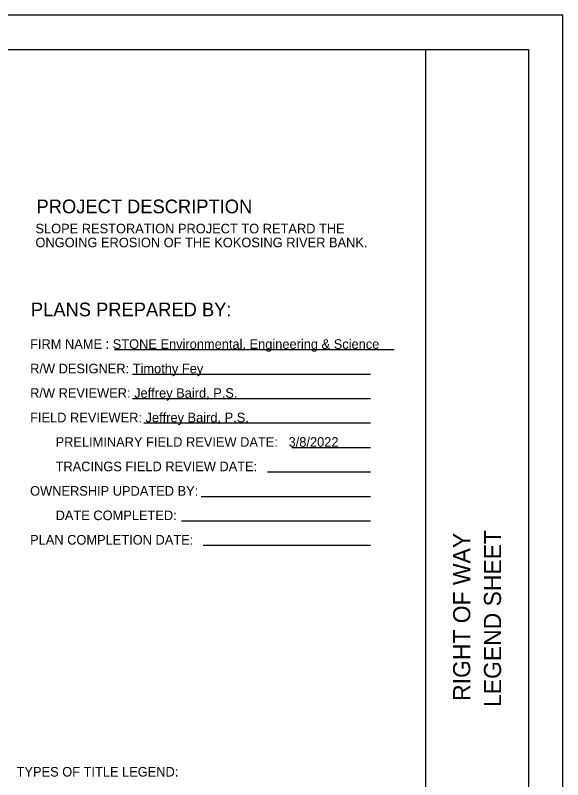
# Model space of a CAD drawing. Extents: x 0 to 104, y 0 to 37.
# Drawn here: x 26.01 to 34, y 10.84 to 22 of the extents above; entities that cross this region are included whole.
import ezdxf

# ---------------------------------------------------------------- set-up
doc = ezdxf.new("R2010")
doc.units = 0
for name, color, linetype in [('SC_Scratch3', 7, 'Continuous'), ('SH_Cut_Line', 7, 'Continuous'), ('SH_Data', 7, 'Continuous'), ('SH_Named_Boundary', 7, 'Continuous')]:
    doc.layers.add(name, color=color, linetype=linetype)

msp = doc.modelspace()

# ---------------------------------------------------------------- linework, layer by layer
at = {"layer": 'SC_Scratch3'}
msp.add_lwpolyline([(0, 0), (34, 0), (34, 22), (0, 22)], close=True, dxfattribs=at)
at = {"layer": 'SH_Data'}
for p, q in [((27.456, 17.121), (31.54, 17.121)), ((27.72, 16.764), (31.193, 16.764)), ((27.72, 16.407), (31.193, 16.407)), ((27.884, 16.05), (31.193, 16.05)), ((30.047, 15.692), (31.193, 15.692)), ((29.69, 15.335), (31.193, 15.335)), ((28.72, 14.978), (31.193, 14.978)), ((28.435, 14.621), (31.193, 14.621)), ((28.75, 14.264), (31.193, 14.264))]:
    msp.add_line(p, q, dxfattribs=at)
at = {"layer": 'SH_Named_Boundary'}
msp.add_line((32, 0.5), (32, 21.5), dxfattribs=at)
msp.add_lwpolyline([(1.5, 21.5), (33.5, 21.5), (33.5, 0.5), (1.5, 0.5)], close=True, dxfattribs=at)

# ---------------------------------------------------------------- texts
at = {"layer": 'SH_Cut_Line'}
for s, p in [('RIGHT OF WAY', (32.65, 11.993)), ('LEGEND SHEET', (33.1, 11.904))]:
    msp.add_text(s, height=0.25, rotation=90, dxfattribs=at).set_placement(p)
at = {"layer": 'SH_Data'}
for s, height, p in [('PROJECT DESCRIPTION', 0.2, (26.317, 19.11)), ('SLOPE RESTORATION PROJECT TO RETARD THE', 0.14, (26.302, 18.817)), ('ONGOING EROSION OF THE KOKOSING RIVER BANK.', 0.14, (26.302, 18.614)), ('PLANS PREPARED BY:', 0.2, (26.236, 17.606)), ('FIRM NAME : STONE Environmental, Engineering & Science', 0.14, (26.224, 17.131)), ('R/W DESIGNER: Timothy Fey', 0.14, (26.224, 16.774)), ('R/W REVIEWER: Jeffrey Baird, P.S.', 0.14, (26.224, 16.417)), ('FIELD REVIEWER: Jeffrey Baird, P.S.', 0.14, (26.224, 16.059)), ('PRELIMINARY FIELD REVIEW DATE:   3/8/2022', 0.14, (26.596, 15.702)), ('TRACINGS FIELD REVIEW DATE: ', 0.14, (26.596, 15.345)), ('OWNERSHIP UPDATED BY: ', 0.14, (26.224, 14.988)), ('DATE COMPLETED: ', 0.14, (26.596, 14.631)), ('PLAN COMPLETION DATE: ', 0.14, (26.224, 14.274)), ('TYPES OF TITLE LEGEND:', 0.14, (26.027, 10.888))]:
    msp.add_text(s, height=height, dxfattribs=at).set_placement(p)

doc.saveas('drawing.dxf')
